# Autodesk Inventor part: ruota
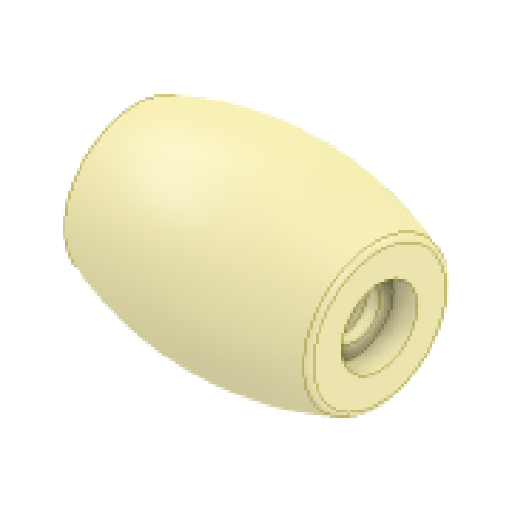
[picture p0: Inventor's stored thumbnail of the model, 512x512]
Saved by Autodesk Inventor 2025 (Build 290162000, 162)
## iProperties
Created: 2025-05
Part Number: ruota
Material: Nylon 6/6
Document SubType Name: Modeling
Designer: R5800u
Density: 1.13 g/cm^3
Appearance: Nylon 6
Author: R5800u
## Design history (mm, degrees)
sketch "Schizzo1"
  geometry: L1 (0, 0)-(-36.77, 36.77); L2 (0, 0)-(-73.48, 0); L3 (-19.6, 48.165)-(-19.6, 0); L4 (0, 0)-(0, 52); L5 (-19.6, 37)-(0, 37); L6 (19.6, 37)-(0, 37); L7 (19.6, 48.165)-(19.6, 0); C1 r 50 at (0, 0); A1 r 52 centre (0, 0) between (-36.77, 36.77) and (-19.6, 48.165); 2 further points
  constraints: 14 end point, 4 point on line, 3 point on circle, 3 symmetric about line, 2 centre point, 2 horizontal, 1 coincident, 1 perpendicular, 1 vertical
  dimensions: "d0" = 100 diameter of C1; "d1" = 2 radial gap between concentric circles of C1 A1; "d3" = 45 deg angle of L2 L1; "d4" = 19.6 distance between parallel lines of L4 L3; "d5" = 37 distance between parallel lines of L2 L5
revolve "Rivoluzione1" sketch "Schizzo1" stored, may be unused: angle "d6" = 90 deg
sketch "Schizzo2"
  geometry: 2 further points
hole "Foro1" sketch "Schizzo2" at (0, 0) diameter "d7" = 5; stored, may be unused: countersink angle "d11" = 90 deg, drill point angle "d13" = 118 deg; dims "d8" = 6, "d9" = 9.4, "d10" = 2, "d12" = 8
fillet "Raccordo1" dims "d14" = 1
sketch "Schizzo3"
  geometry: C1 r 2.5 at (0, 0) reference; C2 r 6 at (0, 0); 1 further point
  constraints: 1 centre point, 1 coincident
  dimensions: "d15" = 12 diameter of C2
extrude "Estrusione1" cut sketch "Schizzo3" distance "d16" = 3.9; taper "d17" = 0 deg
sketch "Schizzo4"
  geometry: C1 r 4 at (0, 0); 1 further point
  constraints: 1 centre point
  dimensions: "d18" = 8 diameter of C1
extrude "Estrusione2" cut sketch "Schizzo4" distance "d19" = 2; taper "d20" = 0 deg
mirror "Speculare2"
node "Solido1"
